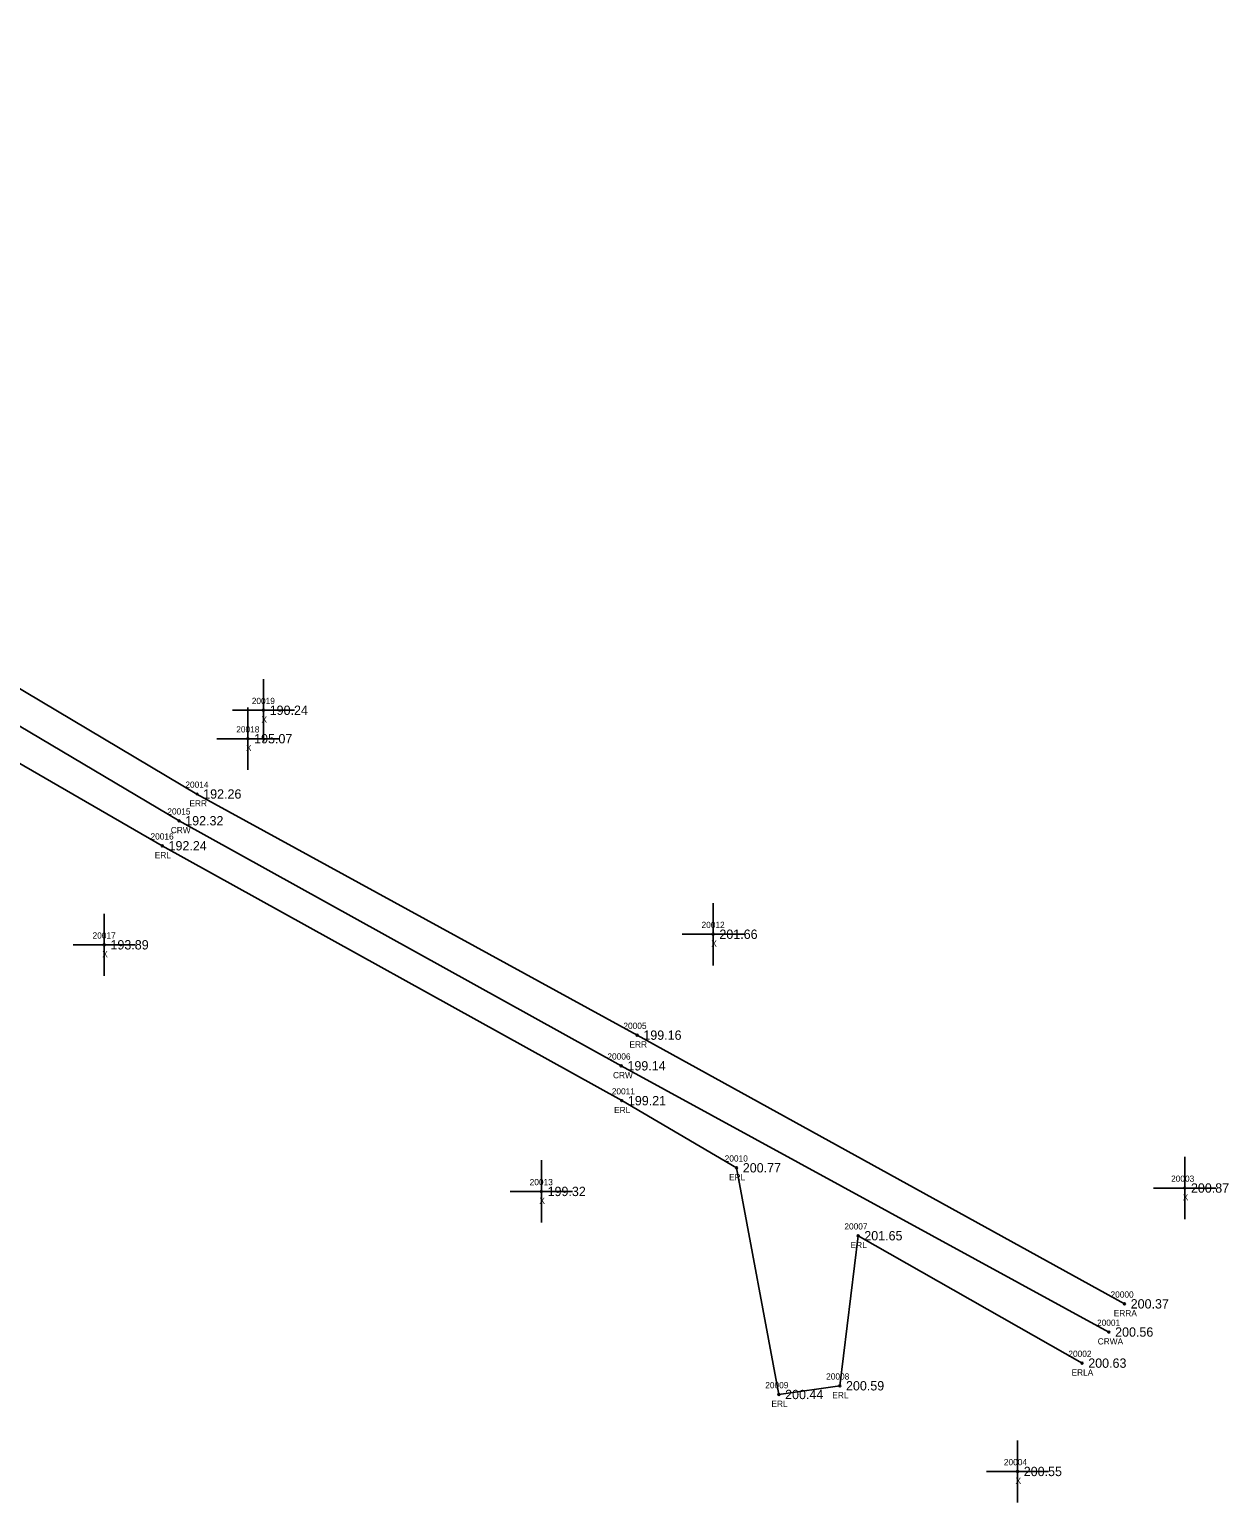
# Model space of a CAD drawing. Extents: x 1970726 to 1971567, y 794829 to 795775.
# Drawn here: x 1971374.6 to 1971567.2, y 794829.2 to 795066 of the extents above; entities that cross this region are included whole.
import ezdxf

# ---------------------------------------------------------------- set-up
doc = ezdxf.new("R2010")
doc.units = 0
for name, color, linetype in [('RD_DTM_BkLn1', 7, 'Continuous'), ('RD_EX_Misc', 7, 'Continuous'), ('RD_EX_Misc_txCode', 7, 'Continuous'), ('RD_EX_Road', 7, 'Continuous'), ('RD_EX_Road_txCode', 7, 'Continuous'), ('RD_EX_TX_Misc_ELEV', 7, 'Continuous'), ('RD_EX_TX_Road_ELEV', 7, 'Continuous'), ('RD_HC_Survey_ELEV', 7, 'Continuous'), ('RD_HC_Survey_txCode', 7, 'Continuous'), ('RD_SMD_Locator', 7, 'Continuous')]:
    doc.layers.add(name, color=color, linetype=linetype)

msp = doc.modelspace()

# ---------------------------------------------------------------- linework, layer by layer
at = {"layer": 'RD_DTM_BkLn1'}
msp.add_lwpolyline([(1971548, 794856.6), (1971469.65, 794899.39), (1971398.6, 794938.78), (1971343.49, 794971.52), (1971282.15, 795020.93), (1971214.82, 795076.24), (1971168.26, 795117.15), (1971077.37, 795216.68), (1971014.25, 795285.1), (1970928, 795384.12), (1970874.41, 795450.05), (1970851.19, 795487.2), (1970834.94, 795528.12), (1970822.6, 795571.11), (1970808.56, 795633.3), (1970801.01, 795695.48), (1970787.01, 795762.98)], dxfattribs=at)
at = {"layer": 'RD_EX_Misc'}
for p, q in [((1971412.17, 794951.54), (1971412.17, 794961.54)), ((1971407.17, 794956.54), (1971417.17, 794956.54)), ((1971409.67, 794946.97), (1971409.67, 794956.97)), ((1971404.67, 794951.97), (1971414.67, 794951.97)), ((1971484.42, 794915.54), (1971484.42, 794925.54)), ((1971386.59, 794913.84), (1971386.59, 794923.84)), ((1971479.42, 794920.54), (1971489.42, 794920.54)), ((1971381.59, 794918.84), (1971391.59, 794918.84)), ((1971456.82, 794874.2), (1971456.82, 794884.2)), ((1971560.18, 794874.75), (1971560.18, 794884.75)), ((1971451.82, 794879.2), (1971461.82, 794879.2)), ((1971555.18, 794879.75), (1971565.18, 794879.75)), ((1971533.32, 794829.19), (1971533.32, 794839.19)), ((1971528.32, 794834.19), (1971538.32, 794834.19))]:
    msp.add_line(p, q, dxfattribs=at)
at = {"layer": 'RD_EX_Road'}
for points in [[(1971550.5, 794861.13), (1971472.2, 794904.32), (1971401.49, 794943.08), (1971346.58, 794975.73), (1971286.05, 795024.56), (1971217.92, 795079.41), (1971172.76, 795121.06), (1971082.31, 795221.27), (1971017.96, 795288.13), (1970931.75, 795387.33), (1970878.11, 795452.95), (1970856.35, 795489.48), (1970840.29, 795529.45), (1970827.57, 795574.31), (1970814.81, 795635.62), (1970805.04, 795696.13), (1970791.39, 795763.83)], [(1971543.68, 794851.6), (1971507.7, 794872.08), (1971504.76, 794847.96), (1971494.98, 794846.56), (1971488.18, 794883), (1971469.72, 794893.79), (1971395.92, 794934.76), (1971339.47, 794967.38), (1971278.34, 795016.59), (1971212.1, 795072.1), (1971165.04, 795113.96), (1971074.42, 795213.48), (1971010.42, 795281.48), (1970922.49, 795383.19), (1970882.25, 795365.41), (1970854.66, 795404.07), (1970871.45, 795443.76), (1970844.39, 795483.83), (1970828.93, 795526.65), (1970817.76, 795568.61), (1970806.82, 795600.57), (1970787.72, 795602.49), (1970770.58, 795591.56)]]:
    msp.add_lwpolyline(points, dxfattribs=at)
at = {"layer": 'RD_SMD_Locator'}
for centre in [(1971412.17, 794956.54), (1971409.67, 794951.97), (1971401.49, 794943.08), (1971398.6, 794938.78), (1971395.92, 794934.76), (1971484.42, 794920.54), (1971386.59, 794918.84), (1971472.2, 794904.32), (1971469.65, 794899.39), (1971469.72, 794893.79), (1971488.18, 794883), (1971456.82, 794879.2), (1971560.18, 794879.75), (1971507.7, 794872.08), (1971550.5, 794861.13), (1971548, 794856.6), (1971543.68, 794851.6), (1971504.76, 794847.96), (1971494.98, 794846.56), (1971533.32, 794834.19)]:
    msp.add_circle(centre, 0.15, dxfattribs=at)

# ---------------------------------------------------------------- texts
at = {"layer": 'RD_EX_Misc_txCode'}
for s, p in [('20019', (1971410.29, 794957.54)), ('20018', (1971407.8, 794952.97)), ('X', (1971411.85, 794954.54)), ('X', (1971409.36, 794949.97)), ('20017', (1971384.71, 794919.84)), ('20012', (1971482.55, 794921.54)), ('X', (1971484.11, 794918.54)), ('X', (1971386.27, 794916.84)), ('20013', (1971454.94, 794880.2)), ('20003', (1971557.99, 794880.75)), ('X', (1971456.5, 794877.2)), ('X', (1971559.87, 794877.75)), ('20004', (1971531.12, 794835.19)), ('X', (1971533, 794832.19))]:
    msp.add_text(s, height=1, dxfattribs=at).set_placement(p)
at = {"layer": 'RD_EX_Road_txCode'}
for s, p in [('20014', (1971399.62, 794944.08)), ('ERR', (1971400.27, 794941.08)), ('20016', (1971394.02, 794935.76)), ('ERL', (1971394.71, 794932.76)), ('20005', (1971470, 794905.32)), ('ERR', (1971470.97, 794902.32)), ('20011', (1971468.13, 794894.79)), ('ERL', (1971468.51, 794891.79)), ('20010', (1971486.27, 794884)), ('ERL', (1971486.97, 794881)), ('20007', (1971505.5, 794873.08)), ('ERL', (1971506.5, 794870.08)), ('20000', (1971548.26, 794862.13)), ('ERRA', (1971548.78, 794859.13)), ('20002', (1971541.49, 794852.6)), ('20008', (1971502.57, 794848.96)), ('ERLA', (1971541.99, 794849.6)), ('20009', (1971492.79, 794847.56)), ('ERL', (1971493.78, 794844.56)), ('ERL', (1971503.56, 794845.96))]:
    msp.add_text(s, height=1, dxfattribs=at).set_placement(p)
at = {"layer": 'RD_EX_TX_Misc_ELEV'}
for s, p in [('190.24', (1971413.17, 794955.79)), ('195.07', (1971410.67, 794951.22)), ('201.66', (1971485.42, 794919.79)), ('193.89', (1971387.59, 794918.09)), ('200.87', (1971561.18, 794879)), ('199.32', (1971457.82, 794878.45)), ('200.55', (1971534.32, 794833.44))]:
    msp.add_text(s, height=1.5, dxfattribs=at).set_placement(p)
at = {"layer": 'RD_EX_TX_Road_ELEV'}
for s, p in [('192.26', (1971402.49, 794942.33)), ('192.24', (1971396.92, 794934.01)), ('199.16', (1971473.2, 794903.57)), ('199.21', (1971470.72, 794893.04)), ('200.77', (1971489.18, 794882.25)), ('201.65', (1971508.7, 794871.33)), ('200.37', (1971551.5, 794860.38)), ('200.63', (1971544.68, 794850.85)), ('200.44', (1971495.98, 794845.81)), ('200.59', (1971505.76, 794847.21))]:
    msp.add_text(s, height=1.5, dxfattribs=at).set_placement(p)
at = {"layer": 'RD_HC_Survey_ELEV'}
for s, p in [('192.32', (1971399.6, 794938.03)), ('199.14', (1971470.65, 794898.64)), ('200.56', (1971549, 794855.85))]:
    msp.add_text(s, height=1.5, dxfattribs=at).set_placement(p)
at = {"layer": 'RD_HC_Survey_txCode'}
for s, p in [('20015', (1971396.73, 794939.78)), ('CRW', (1971397.28, 794936.78)), ('20006', (1971467.43, 794900.39)), ('CRW', (1971468.33, 794897.39)), ('20001', (1971546.09, 794857.6)), ('CRWA', (1971546.2, 794854.6))]:
    msp.add_text(s, height=1, dxfattribs=at).set_placement(p)

doc.saveas('drawing.dxf')
